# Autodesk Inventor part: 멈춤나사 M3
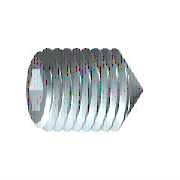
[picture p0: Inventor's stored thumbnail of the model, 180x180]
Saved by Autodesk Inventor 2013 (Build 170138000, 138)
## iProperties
IsCustomPart: 1
Created: 2012-02
Part Number: 멈춤나사 M3
Material: 강철, 연강
Description: 6각 소켓 머리 없는 멈춤 나사
Document SubType Name: Modeling
Standard: KS B 1028
Designer: mduedu
Standards Organization: KS
Language: ko-KR
Size Designation: 원추점 M3x6
Categories: <MemberInstance><Categories><Category DisplayName="조임쇠" InternalName="e4da775c-781d-43d5-af7c-5136215cf5a6" Mnemonic="FSTN"><Category DisplayName="볼트" InternalN
Density: 1 g/cm^3
Author: mduedu
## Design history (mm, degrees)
sketch "스케치1"
  geometry: L1 (0, 0)-(3.5, 0); L2 (6, 0.866)-(6, 1.5); L3 (6, 1.5)-(0, 1.5); L4 (6, 0.866)-(4, 0.866); L5 (4, 0.866)-(3.5, 0); L6 (0, -0.3)-(0, 1.8) reference; L7 (0, 1.5)-(0, 0)
  constraints: 13 end point, 3 parallel, 1 collinear, 1 perpendicular, 1 point on line
  dimensions: "d0" = 2 distance of L2.start L4.end (= INTI); "d1" = 60 deg angle of L5 L1; "d2" = 3 diameter of L3 L1 (= NND); "d3" = 1.73205 diameter of L4 L1 (= 1.1547 x SW); "d5" = 6 distance from line of L2 L3.end (= NLG)
revolve "본체" sketch "스케치1" stored, may be unused: angle "d6" = 90 deg
sketch "스케치2"
  geometry: L1 (-0.433, 0.75)-(0.433, 0.75); L2 (0.433, 0.75)-(0.866, 0); L3 (0.866, 0)-(0.433, -0.75); L4 (0.433, -0.75)-(-0.433, -0.75); L5 (-0.433, -0.75)-(-0.866, 0); L6 (-0.866, 0)-(-0.433, 0.75); 3 further points
  constraints: 12 end point, 1 coincident, 1 horizontal, 13 other
extrude "슬롯" join sketch "스케치2" taper "d7" = 0 deg; stored distance "d21" = 10
workaxis "Work Axis1"
workplane "Work Plane1"
body "Solid1"
feature "스레드" dims "d12" = 6 (= NLG), "d13" = 0
chamfer "모따기1" distance "d8" = 1.35 (computed from NND, SPD, FAWI); stored, may be unused: angle "d9" = 45 deg (= FAWI), second distance "d34" = 1.35 (computed from NND, SPD, FAWI)
chamfer "모따기2" distance "d10" = 0.30673 (= -0.5 x GD1 + 0.5 x NND); stored, may be unused: angle "d11" = 45 deg (= FAWI), second distance "d35" = 0.30673 (= -0.5 x GD1 + 0.5 x NND)
other parameters: "NND" = 3 [user parameter; used in 5 equation terms], "NLG" = 6 [user parameter; used in 2 equation terms], "INTI" = 2 [user parameter; used in 1 equation term], "FAWI" = 45 deg [user parameter; used in 4 equation terms], "SW" = 1.5 [user parameter; used in 2 equation terms], "GD1" = 2.38655 (= THREADDIA - 1.2269 x PTC) [user parameter; used in 2 equation terms], "d4" = 0, "FAWI1" = 45 deg [user parameter], "SPD" = 0.3 [user parameter; used in 2 equation terms], "d36" = 0, "d37" = 0, "GUL" = 0.30673 (= 0.61345 x PTC) [user parameter], "TOA" = 30 deg [user parameter], "THREADDIA" = 3 [user parameter; used in 1 equation term], "PTC" = 0.5 [user parameter; used in 4 equation terms], "GAL" = 0.30673 (= 0.61345 x PTC) [user parameter], "E0" = 1.7325 (= 1.155 x SW) [user parameter]
